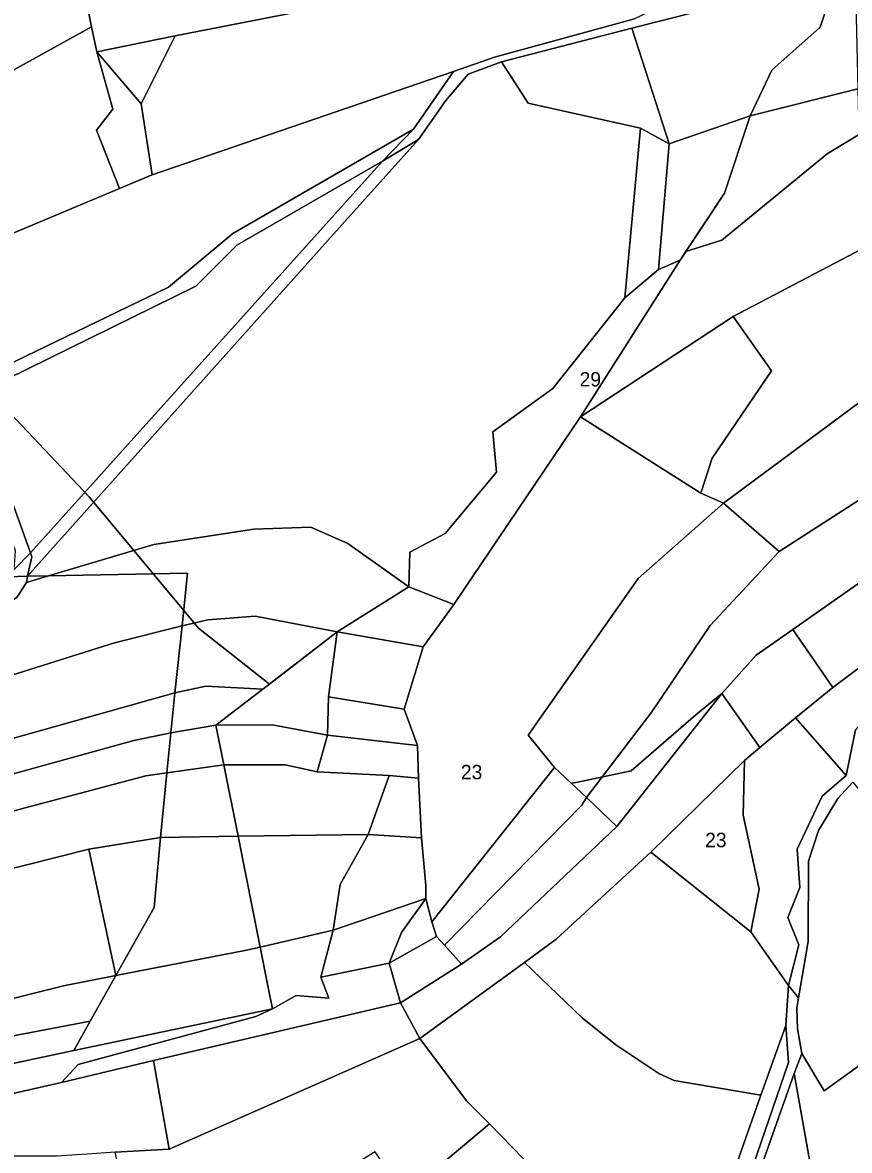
# Model space of a CAD drawing. Extents: x -521261 to -517465, y -1182764 to -1179456.
# Drawn here: x -520234.1 to -519947.3, y -1181487.6 to -1181096.5 of the extents above; entities that cross this region are included whole.
import ezdxf

# ---------------------------------------------------------------- set-up
doc = ezdxf.new("R2010")
doc.units = 0
for name, color, linetype in [('95560013', 7, 'Continuous'), ('95610013', 7, 'Continuous'), ('95620013', 7, 'Continuous'), ('95630013', 7, 'Continuous'), ('95640013', 7, 'Continuous'), ('95660013', 7, 'Continuous')]:
    doc.layers.add(name, color=color, linetype=linetype)

msp = doc.modelspace()

# ---------------------------------------------------------------- linework, layer by layer
at = {"layer": '95560013'}
for points in [[(-519951.3, -1181365.5), (-519946.1, -1181359.91), (-519939.45, -1181367.89), (-519928.16, -1181391.65), (-519920.19, -1181404.39), (-519905.49, -1181435.85), (-519925.87, -1181445.17), (-519955.99, -1181466.92), (-519963.8, -1181454), (-519965.32, -1181445.39), (-519965.55, -1181438.1), (-519964.94, -1181434.67), (-519961.63, -1181415.2), (-519961.5, -1181387.25), (-519958.05, -1181376.65)], [(-520016.12, -1181384.16), (-519981.47, -1181411.84), (-519968.45, -1181430.45), (-519969.29, -1181444.31), (-519978.05, -1181468.4), (-520008.07, -1181463.33), (-520013.39, -1181460.97), (-520028.29, -1181450.94), (-520039.97, -1181441.63), (-520059.93, -1181422.38), (-520049.04, -1181414.3)], [(-520059.93, -1181422.38), (-520039.97, -1181441.63), (-520028.29, -1181450.94), (-520013.39, -1181460.97), (-520008.07, -1181463.33), (-519978.05, -1181468.4), (-519996.47, -1181521.04), (-520018.3, -1181517.23), (-520033.36, -1181509.68), (-520056.39, -1181494.56), (-520072.1, -1181478.37), (-520080.04, -1181470.38), (-520096.25, -1181448.83)], [(-519881.06, -1181420.17), (-519881.55, -1181422.98), (-519869.95, -1181467.47), (-519852.44, -1181544.73), (-519850.41, -1181556.71), (-519864.72, -1181556.65), (-519890.05, -1181563.82), (-519912.71, -1181573.25), (-519943.88, -1181587.97), (-519966.4, -1181460.95), (-519963.8, -1181454), (-519955.99, -1181466.92), (-519925.87, -1181445.17), (-519905.49, -1181435.85), (-519894.06, -1181430.89)], [(-519968.45, -1181457.09), (-519991.41, -1181524.14), (-520014.78, -1181559.72), (-520031.11, -1181570.27), (-520050.83, -1181581.91), (-520073.58, -1181593.67), (-520103.45, -1181603.73), (-520078.6, -1181591.68), (-520045.34, -1181574.36), (-520019.1, -1181556.48), (-519998.04, -1181525.72), (-519996.47, -1181521.04), (-519978.05, -1181468.4), (-519969.29, -1181444.31)], [(-519980.74, -1181501.54), (-519966.4, -1181460.95), (-519943.88, -1181587.97), (-519965.56, -1181598.45)]]:
    msp.add_lwpolyline(points, close=True, dxfattribs=at)
msp.add_lwpolyline([(-519991.41, -1181524.14), (-519968.45, -1181457.09), (-519969.29, -1181444.31), (-519968.45, -1181430.45), (-519964.94, -1181434.67), (-519965.55, -1181438.1), (-519965.32, -1181445.39), (-519963.8, -1181454), (-519966.4, -1181460.95), (-519980.74, -1181501.54)], dxfattribs=at)
at = {"layer": '95610013'}
for points in [[(-520022.75, -1181098.44), (-520009.75, -1181138.53), (-520019.71, -1181133.07), (-520058.75, -1181124.43), (-520067.99, -1181110.15)], [(-520067.99, -1181110.15), (-520058.75, -1181124.43), (-520019.71, -1181133.07), (-520025.14, -1181191.93), (-520050.1, -1181223.4), (-520070.9, -1181238.45), (-520069.69, -1181252.35), (-520087.51, -1181273.69), (-520099.76, -1181280.17), (-520100.07, -1181292.11), (-520121.29, -1181277.16), (-520134.04, -1181271.49), (-520153.79, -1181272.12), (-520188.51, -1181277.48), (-520225.08, -1181288.33), (-520232.39, -1181288.47), (-520122.24, -1181165.49), (-520096.77, -1181137.02), (-520087.2, -1181123.58), (-520079.52, -1181114.4)], [(-519944.34, -1181119.43), (-519943.14, -1181175.07), (-519987.58, -1181198.4), (-520040.59, -1181233.21), (-520006.04, -1181178.85), (-519990.56, -1181155.71), (-519981.67, -1181128.85)], [(-520019.71, -1181133.07), (-520009.75, -1181138.53), (-520013.54, -1181182.09), (-520025.14, -1181191.93)], [(-519856.08, -1181205.45), (-519852.38, -1181211.59), (-519868.58, -1181228.75), (-519891.75, -1181243.42), (-519901.14, -1181260.79), (-519966.9, -1181306.97), (-519979.58, -1181315.88), (-519991.48, -1181329.17), (-520027.93, -1181375.27), (-520038.45, -1181365.21), (-520015.84, -1181335.46), (-519995.54, -1181305.59), (-519971.69, -1181279.96)], [(-519990.97, -1181263.2), (-519971.69, -1181279.96), (-519995.54, -1181305.59), (-520015.84, -1181335.46), (-520038.45, -1181365.21), (-520049.55, -1181354.85), (-520058.68, -1181343.58), (-520020.61, -1181289.25)], [(-520153.79, -1181272.12), (-520134.04, -1181271.49), (-520121.29, -1181277.16), (-520100.07, -1181292.11), (-520124.95, -1181307.73), (-520153.36, -1181302.35), (-520169.85, -1181303.56), (-520178.71, -1181305.72), (-520176.89, -1181287.4), (-520225.08, -1181288.33), (-520188.51, -1181277.48)], [(-520232.39, -1181288.47), (-520232.63, -1181290.61), (-520236.03, -1181295.81), (-520255.53, -1181307.58), (-520287.18, -1181334.21), (-520293.89, -1181340.02), (-520317.68, -1181359.9), (-520321.39, -1181363.01), (-520341.1, -1181374.15), (-520355.78, -1181386.73), (-520385.73, -1181412.26), (-520405.58, -1181428.65), (-520445.12, -1181472.67), (-520448.41, -1181473.09), (-520408.16, -1181427.45), (-520391.32, -1181413.46), (-520359.89, -1181386.72), (-520345.57, -1181373.71), (-520321.57, -1181359.96), (-520292.94, -1181335.11), (-520256.36, -1181304.34), (-520239.14, -1181288.67)], [(-520176.89, -1181287.4), (-520178.71, -1181305.72), (-520202.19, -1181311.58), (-520269.09, -1181332.61), (-520287.18, -1181334.21), (-520255.53, -1181307.58), (-520236.03, -1181295.81), (-520232.63, -1181290.61), (-520225.08, -1181288.33)], [(-520225.08, -1181288.33), (-520232.63, -1181290.61), (-520232.39, -1181288.47)], [(-520202.19, -1181311.58), (-520178.71, -1181305.72), (-520181.27, -1181328.86), (-520253.27, -1181349.13), (-520292.48, -1181357.65), (-520293.89, -1181340.02), (-520287.18, -1181334.21), (-520269.09, -1181332.61)], [(-520169.85, -1181303.56), (-520153.36, -1181302.35), (-520124.95, -1181307.73), (-520150.71, -1181327.64), (-520170.48, -1181326.56), (-520181.27, -1181328.86), (-520178.71, -1181305.72)], [(-520182.58, -1181342.83), (-520195.46, -1181345.45), (-520246.59, -1181359.49), (-520270.2, -1181364.68), (-520301.73, -1181370.53), (-520292.48, -1181357.65), (-520253.27, -1181349.13), (-520181.27, -1181328.86)], [(-520170.48, -1181326.56), (-520150.71, -1181327.64), (-520166.98, -1181340.15), (-520182.58, -1181342.83), (-520181.27, -1181328.86)], [(-519991.48, -1181329.17), (-519978.38, -1181347.83), (-519983.72, -1181352.35), (-520016.12, -1181384.16), (-520049.04, -1181414.3), (-520059.93, -1181422.38), (-520096.25, -1181448.83), (-520102.93, -1181436.39), (-520081.87, -1181423.03), (-520068.35, -1181413.48), (-520027.93, -1181375.27)], [(-520166.98, -1181340.15), (-520164.29, -1181353.89), (-520184.06, -1181356.65), (-520182.58, -1181342.83)], [(-520195.46, -1181345.45), (-520182.58, -1181342.83), (-520184.06, -1181356.65), (-520191.33, -1181357.73), (-520249.83, -1181373.13), (-520302.68, -1181384.22), (-520337.44, -1181387.17), (-520355.78, -1181386.73), (-520341.1, -1181374.15), (-520301.73, -1181370.53), (-520270.2, -1181364.68), (-520246.59, -1181359.49)], [(-520191.33, -1181357.73), (-520184.06, -1181356.65), (-520186.19, -1181379.03), (-520211.1, -1181383.08), (-520254.64, -1181394.05), (-520290.16, -1181400.78), (-520324.33, -1181405.78), (-520365.37, -1181407.48), (-520385.73, -1181412.26), (-520355.78, -1181386.73), (-520337.44, -1181387.17), (-520302.68, -1181384.22), (-520249.83, -1181373.13)], [(-520164.29, -1181353.89), (-520159.29, -1181378.66), (-520186.19, -1181379.03), (-520184.06, -1181356.65)], [(-520211.1, -1181383.08), (-520186.19, -1181379.03), (-520188.37, -1181403.38), (-520201.65, -1181426.98)], [(-520186.19, -1181379.03), (-520159.29, -1181378.66), (-520151.63, -1181417.07), (-520156.97, -1181418.3), (-520201.65, -1181426.98), (-520188.37, -1181403.38)], [(-520211.1, -1181383.08), (-520201.65, -1181426.98), (-520219.86, -1181430.55), (-520255.51, -1181439.46), (-520313.09, -1181448.84), (-520364.32, -1181456), (-520445.12, -1181472.67), (-520405.58, -1181428.65), (-520385.73, -1181412.26), (-520365.37, -1181407.48), (-520324.33, -1181405.78), (-520290.16, -1181400.78), (-520254.64, -1181394.05)], [(-520151.63, -1181417.07), (-520148.84, -1181431.11), (-520147.36, -1181438.44), (-520216.32, -1181452.99), (-520210.56, -1181442.77), (-520201.65, -1181426.98), (-520156.97, -1181418.3)], [(-520219.86, -1181430.55), (-520201.65, -1181426.98), (-520210.56, -1181442.77), (-520310.06, -1181461.77), (-520313.09, -1181448.84), (-520255.51, -1181439.46)], [(-520216.32, -1181452.99), (-520307.52, -1181472.34), (-520310.06, -1181461.77), (-520210.56, -1181442.77)]]:
    msp.add_lwpolyline(points, close=True, dxfattribs=at)
at = {"layer": '95620013'}
for points in [[(-519886.73, -1181149.7), (-519872.92, -1181175.6), (-519990.97, -1181263.2), (-519998.85, -1181259.72), (-519994.9, -1181247.54), (-519974.28, -1181217.29), (-519987.58, -1181198.4), (-519943.14, -1181175.07)], [(-519872.92, -1181175.6), (-519856.08, -1181205.45), (-519971.69, -1181279.96), (-519990.97, -1181263.2)], [(-519987.58, -1181198.4), (-519974.28, -1181217.29), (-519994.9, -1181247.54), (-519998.85, -1181259.72), (-520040.59, -1181233.21)], [(-520040.59, -1181233.21), (-519998.85, -1181259.72), (-519990.97, -1181263.2), (-520020.61, -1181289.25), (-520058.68, -1181343.58), (-520049.55, -1181354.85), (-520092.06, -1181408.32), (-520094.21, -1181400.28), (-520094.14, -1181395.72), (-520095.71, -1181379.23), (-520096.74, -1181358.49), (-520097.13, -1181347.16), (-520101.66, -1181334.59), (-520095.13, -1181312.91), (-520084.5, -1181298.3)], [(-520100.07, -1181292.11), (-520084.5, -1181298.3), (-520095.13, -1181312.91), (-520124.95, -1181307.73)], [(-520150.71, -1181327.64), (-520124.95, -1181307.73), (-520127.97, -1181330.34), (-520128.29, -1181343.57), (-520147.46, -1181339.96), (-520166.98, -1181340.15)], [(-520095.13, -1181312.91), (-520101.66, -1181334.59), (-520127.97, -1181330.34), (-520124.95, -1181307.73)], [(-520127.97, -1181330.34), (-520101.66, -1181334.59), (-520097.13, -1181347.16), (-520128.29, -1181343.57)], [(-520166.98, -1181340.15), (-520147.46, -1181339.96), (-520128.29, -1181343.57), (-520131.91, -1181356.33), (-520142.97, -1181353.92), (-520164.29, -1181353.89)], [(-520097.13, -1181347.16), (-520096.74, -1181358.49), (-520106.91, -1181357.61), (-520131.91, -1181356.33), (-520128.29, -1181343.57)], [(-519984.11, -1181371.39), (-519978.54, -1181396.94), (-519981.47, -1181411.84), (-520016.12, -1181384.16), (-519983.72, -1181352.35)], [(-520164.29, -1181353.89), (-520142.97, -1181353.92), (-520131.91, -1181356.33), (-520106.91, -1181357.61), (-520114.22, -1181378.03), (-520159.29, -1181378.66)], [(-520049.55, -1181354.85), (-520038.45, -1181365.21), (-520040.12, -1181367.85), (-520087.7, -1181416.4), (-520090.47, -1181413.37), (-520092.06, -1181408.32)], [(-520106.91, -1181357.61), (-520096.74, -1181358.49), (-520095.71, -1181379.23), (-520114.22, -1181378.03)], [(-520040.12, -1181367.85), (-520038.45, -1181365.21), (-520027.93, -1181375.27), (-520068.35, -1181413.48), (-520081.87, -1181423.03), (-520087.7, -1181416.4)], [(-520159.29, -1181378.66), (-520114.22, -1181378.03), (-520123.93, -1181395.37), (-520126.37, -1181411.25), (-520151.63, -1181417.07)], [(-520095.71, -1181379.23), (-520094.14, -1181395.72), (-520094.21, -1181400.28), (-520126.37, -1181411.25), (-520123.93, -1181395.37), (-520114.22, -1181378.03)], [(-520126.37, -1181411.25), (-520094.21, -1181400.28), (-520102.68, -1181412.01), (-520106.92, -1181422.67), (-520130.56, -1181427.5)], [(-520094.21, -1181400.28), (-520092.06, -1181408.32), (-520090.47, -1181413.37), (-520106.92, -1181422.67), (-520102.68, -1181412.01)], [(-520126.37, -1181411.25), (-520130.56, -1181427.5), (-520127.78, -1181434.85), (-520139.12, -1181433.91), (-520147.36, -1181438.44), (-520148.84, -1181431.11), (-520151.63, -1181417.07)], [(-520087.7, -1181416.4), (-520081.87, -1181423.03), (-520102.93, -1181436.39), (-520106.92, -1181422.67), (-520090.47, -1181413.37)], [(-520106.92, -1181422.67), (-520102.93, -1181436.39), (-520188.68, -1181456.43), (-520220.56, -1181464.03), (-520214.82, -1181457.85), (-520153.14, -1181441.18), (-520147.36, -1181438.44), (-520139.12, -1181433.91), (-520127.78, -1181434.85), (-520130.56, -1181427.5)], [(-520147.36, -1181438.44), (-520153.14, -1181441.18), (-520214.82, -1181457.85), (-520220.56, -1181464.03), (-520249.84, -1181470.67), (-520276.65, -1181475.26), (-520305.37, -1181477.77), (-520307.98, -1181477.97), (-520307.52, -1181472.34), (-520216.32, -1181452.99)], [(-520102.93, -1181436.39), (-520096.25, -1181448.83), (-520183.26, -1181487.11), (-520188.68, -1181456.43)], [(-520080.04, -1181470.38), (-520072.1, -1181478.37), (-520097.97, -1181500.05), (-520102.02, -1181502.48), (-520111.72, -1181488.08), (-520140.88, -1181505.85), (-520171.13, -1181520), (-520198.96, -1181527.88), (-520198.13, -1181505.28), (-520201.97, -1181488.21), (-520183.26, -1181487.11), (-520096.25, -1181448.83)], [(-520220.56, -1181464.03), (-520188.68, -1181456.43), (-520183.26, -1181487.11), (-520201.97, -1181488.21), (-520211.67, -1181488.9), (-520222.29, -1181489.55), (-520248.06, -1181489.62), (-520277.86, -1181490.96), (-520303.01, -1181492.71), (-520305.37, -1181477.77), (-520276.65, -1181475.26), (-520249.84, -1181470.67)], [(-520056.39, -1181494.56), (-520079.5, -1181516.84), (-520096.12, -1181530.34), (-520122.34, -1181546.18), (-520150.55, -1181560.01), (-520174.55, -1181568.61), (-520208.16, -1181578.29), (-520204.49, -1181561.93), (-520102.02, -1181502.48), (-520097.97, -1181500.05), (-520072.1, -1181478.37)]]:
    msp.add_lwpolyline(points, close=True, dxfattribs=at)
at = {"layer": '95630013'}
for points in [[(-519970.42, -1181083.14), (-519951.75, -1181081.08), (-519957.49, -1181098.06), (-519974.19, -1181113.01), (-519981.67, -1181128.85), (-520009.75, -1181138.53), (-520022.75, -1181098.44), (-520000.75, -1181092.9)], [(-519949.41, -1181080.84), (-519945.25, -1181079.6), (-519944.34, -1181119.43), (-519981.67, -1181128.85), (-519974.19, -1181113.01), (-519957.49, -1181098.06), (-519951.75, -1181081.08)]]:
    msp.add_lwpolyline(points, close=True, dxfattribs=at)
at = {"layer": '95640013'}
for points in [[(-519984.22, -1181051.71), (-520073.26, -1181079.95), (-520181.15, -1181101.08), (-520208.33, -1181106.65), (-520210.11, -1181097.99), (-520214.23, -1181077.46), (-520069.91, -1181056.82), (-520036.68, -1181046.43)], [(-519984.22, -1181051.71), (-519971.7, -1181060.63), (-519957.06, -1181073.24), (-520007.71, -1181088.34), (-520021.78, -1181095.18), (-520070.4, -1181108.55), (-520084.62, -1181113.41), (-520189.15, -1181149.27), (-520192.88, -1181124.68), (-520181.15, -1181101.08), (-520073.26, -1181079.95)], [(-520210.11, -1181097.99), (-520243.42, -1181116.34), (-520272.96, -1181130.65), (-520281.95, -1181113.37), (-520289.13, -1181105.34), (-520214.23, -1181077.46)], [(-520208.33, -1181106.65), (-520202.7, -1181126.58), (-520208.38, -1181133.79), (-520200.46, -1181154.03), (-520254.49, -1181176.66), (-520288.03, -1181193.76), (-520297.05, -1181192.49), (-520302.49, -1181183.79), (-520304.08, -1181171.38), (-520302.27, -1181151.64), (-520287.43, -1181140.94), (-520292.51, -1181161.26), (-520277.55, -1181144.55), (-520279.13, -1181132.17), (-520272.96, -1181130.65), (-520243.42, -1181116.34), (-520210.11, -1181097.99)], [(-520181.15, -1181101.08), (-520192.88, -1181124.68), (-520208.33, -1181106.65)], [(-520192.88, -1181124.68), (-520189.15, -1181149.27), (-520200.46, -1181154.03), (-520208.38, -1181133.79), (-520202.7, -1181126.58), (-520208.33, -1181106.65)], [(-520098.46, -1181133.43), (-520161.15, -1181169.69), (-520183.49, -1181188.27), (-520261.22, -1181225.79), (-520261.82, -1181224.94), (-520288.03, -1181193.76), (-520254.49, -1181176.66), (-520200.46, -1181154.03), (-520189.15, -1181149.27), (-520084.62, -1181113.41)], [(-520009.75, -1181138.53), (-519981.67, -1181128.85), (-519990.56, -1181155.71), (-520006.04, -1181178.85), (-520013.54, -1181182.09)], [(-520109.27, -1181144.59), (-520159.71, -1181173.72), (-520173.94, -1181187.85), (-520246.91, -1181223.77), (-520248.19, -1181228.92), (-520250.09, -1181234), (-520243.27, -1181247.26), (-520231.33, -1181280.35), (-520236.97, -1181286.19), (-520236.52, -1181279.68), (-520238.76, -1181273.9), (-520247.52, -1181249.42), (-520251.17, -1181239.95), (-520261.22, -1181225.79), (-520183.49, -1181188.27), (-520161.15, -1181169.69), (-520098.46, -1181133.43)], [(-520109.27, -1181144.59), (-520096.77, -1181137.02), (-520122.24, -1181165.49), (-520232.39, -1181288.47), (-520230.87, -1181281.73), (-520231.33, -1181280.35)], [(-520159.71, -1181173.72), (-520109.27, -1181144.59), (-520231.33, -1181280.35), (-520243.27, -1181247.26), (-520250.09, -1181234), (-520248.19, -1181228.92), (-520246.91, -1181223.77), (-520173.94, -1181187.85)], [(-520013.54, -1181182.09), (-520006.04, -1181178.85), (-520040.59, -1181233.21), (-520084.5, -1181298.3), (-520100.07, -1181292.11), (-520099.76, -1181280.17), (-520087.51, -1181273.69), (-520069.69, -1181252.35), (-520070.9, -1181238.45), (-520050.1, -1181223.4), (-520025.14, -1181191.93)], [(-519751.87, -1181190.47), (-519734.37, -1181182.89), (-519728.68, -1181193.73), (-519750.87, -1181207.64), (-519774.62, -1181212.01), (-519786.76, -1181215.56), (-519829.59, -1181238.74), (-519874.64, -1181267.05), (-519879.94, -1181274.06), (-519908.9, -1181293.64), (-519925.73, -1181306.64), (-519953.04, -1181327.12), (-519966.9, -1181306.97), (-519901.14, -1181260.79), (-519826.46, -1181216.65), (-519791.66, -1181201.16), (-519778.56, -1181195.39)], [(-520230.87, -1181281.73), (-520232.39, -1181288.47), (-520239.14, -1181288.67), (-520236.97, -1181286.19), (-520231.33, -1181280.35)], [(-519966.9, -1181306.97), (-519953.04, -1181327.12), (-519965.99, -1181337.63), (-519978.38, -1181347.83), (-519991.48, -1181329.17), (-519979.58, -1181315.88)], [(-519920.76, -1181313.19), (-519945.15, -1181341.8), (-519948.46, -1181357.6), (-519965.99, -1181337.63), (-519953.04, -1181327.12), (-519925.73, -1181306.64)], [(-519978.38, -1181347.83), (-519965.99, -1181337.63), (-519948.46, -1181357.6), (-519956.74, -1181364.72), (-519965.37, -1181383.15), (-519964.45, -1181396.37), (-519968.69, -1181406.86), (-519964.87, -1181416.32), (-519968.45, -1181430.45), (-519981.47, -1181411.84), (-519978.54, -1181396.94), (-519984.11, -1181371.39), (-519983.72, -1181352.35)]]:
    msp.add_lwpolyline(points, close=True, dxfattribs=at)
for points in [[(-520000.75, -1181092.9), (-520022.75, -1181098.44), (-520067.99, -1181110.15), (-520079.52, -1181114.4), (-520087.2, -1181123.58), (-520096.77, -1181137.02), (-520109.27, -1181144.59), (-520098.46, -1181133.43), (-520084.62, -1181113.41), (-520070.4, -1181108.55), (-520021.78, -1181095.18)], [(-519946.1, -1181359.91), (-519951.3, -1181365.5), (-519958.05, -1181376.65), (-519961.5, -1181387.25), (-519961.63, -1181415.2), (-519964.94, -1181434.67), (-519968.45, -1181430.45), (-519964.87, -1181416.32), (-519968.69, -1181406.86), (-519964.45, -1181396.37), (-519965.37, -1181383.15), (-519956.74, -1181364.72), (-519948.46, -1181357.6), (-519945.15, -1181341.8)]]:
    msp.add_lwpolyline(points, dxfattribs=at)
at = {"layer": '95660013'}
for points in [[(-519804, -1181096), (-519877.5, -1181096.5), (-519906.5, -1181112.5), (-519955, -1181142), (-519991.5, -1181172), (-520000, -1181174.62), (-520004.04, -1181175.86), (-519990.56, -1181155.71), (-519981.67, -1181128.85), (-520009.75, -1181138.53), (-520013.54, -1181182.09), (-520025.14, -1181191.93), (-520050.1, -1181223.4), (-520070.9, -1181238.45), (-520069.69, -1181252.35), (-520087.51, -1181273.69), (-520099.76, -1181280.17), (-520100.07, -1181292.11), (-520124.95, -1181307.73), (-520148.41, -1181325.86), (-520173, -1181306.5), (-520211, -1181261), (-520246, -1181224)], [(-519943.14, -1181175.07), (-519987.58, -1181198.4), (-520040.59, -1181233.21), (-520006.04, -1181178.85), (-520004.04, -1181175.86), (-520000, -1181174.62), (-519991.5, -1181172), (-519955, -1181142), (-519906.5, -1181112.5)], [(-520307.52, -1181472.34), (-520216.32, -1181452.99), (-520147.36, -1181438.44), (-520148.84, -1181431.11), (-520151.63, -1181417.07), (-520159.29, -1181378.66), (-520164.29, -1181353.89), (-520166.98, -1181340.15), (-520150.71, -1181327.64), (-520148.41, -1181325.86), (-520124.95, -1181307.73), (-520100.07, -1181292.11), (-520084.5, -1181298.3), (-520040.59, -1181233.21), (-519987.58, -1181198.4), (-519943.14, -1181175.07)], [(-519856.08, -1181205.45), (-519971.69, -1181279.96), (-519990.97, -1181263.2), (-520020.61, -1181289.25), (-520058.68, -1181343.58), (-520049.55, -1181354.85), (-520043.81, -1181360.21), (-520038.45, -1181365.21), (-520027.93, -1181375.27), (-520068.35, -1181413.48), (-520081.87, -1181423.03), (-520102.93, -1181436.39), (-520096.25, -1181448.83), (-520080.04, -1181470.38), (-520072.1, -1181478.37), (-520056.39, -1181494.56)], [(-519901.14, -1181260.79), (-519966.9, -1181306.97), (-519979.58, -1181315.88), (-519991.48, -1181329.17), (-520000.5, -1181336.5), (-520023, -1181356), (-520042, -1181360), (-520043.81, -1181360.21), (-520049.55, -1181354.85), (-520058.68, -1181343.58), (-520020.61, -1181289.25), (-519990.97, -1181263.2), (-519971.69, -1181279.96), (-519856.08, -1181205.45)], [(-520246, -1181224), (-520211, -1181261), (-520173, -1181306.5), (-520148.41, -1181325.86), (-520150.71, -1181327.64), (-520166.98, -1181340.15), (-520164.29, -1181353.89), (-520159.29, -1181378.66), (-520151.63, -1181417.07), (-520148.84, -1181431.11), (-520147.36, -1181438.44), (-520216.32, -1181452.99), (-520307.52, -1181472.34)], [(-519945.15, -1181341.8), (-519948.46, -1181357.6), (-519956.74, -1181364.72), (-519965.37, -1181383.15), (-519964.45, -1181396.37), (-519968.69, -1181406.86), (-519964.87, -1181416.32), (-519968.45, -1181430.45), (-519981.47, -1181411.84), (-519978.54, -1181396.94), (-519984.11, -1181371.39), (-519983.72, -1181352.35), (-519978.38, -1181347.83), (-519991.48, -1181329.17), (-519979.58, -1181315.88), (-519966.9, -1181306.97), (-519901.14, -1181260.79)], [(-520056.39, -1181494.56), (-520072.1, -1181478.37), (-520080.04, -1181470.38), (-520096.25, -1181448.83), (-520102.93, -1181436.39), (-520081.87, -1181423.03), (-520068.35, -1181413.48), (-520027.93, -1181375.27), (-520038.45, -1181365.21), (-520043.81, -1181360.21), (-520042, -1181360), (-520023, -1181356), (-520000.5, -1181336.5), (-519991.48, -1181329.17), (-519978.38, -1181347.83), (-519983.72, -1181352.35), (-520016.12, -1181384.16), (-519981.47, -1181411.84), (-519968.45, -1181430.45), (-519964.87, -1181416.32), (-519968.69, -1181406.86), (-519964.45, -1181396.37), (-519965.37, -1181383.15), (-519956.74, -1181364.72), (-519948.46, -1181357.6), (-519945.15, -1181341.8)]]:
    msp.add_lwpolyline(points, dxfattribs=at)
for points in [[(-520013.54, -1181182.09), (-520009.75, -1181138.53), (-519981.67, -1181128.85), (-519990.56, -1181155.71), (-520006.04, -1181178.85), (-520040.59, -1181233.21), (-520084.5, -1181298.3), (-520100.07, -1181292.11), (-520099.76, -1181280.17), (-520087.51, -1181273.69), (-520069.69, -1181252.35), (-520070.9, -1181238.45), (-520050.1, -1181223.4), (-520025.14, -1181191.93)], [(-520016.12, -1181384.16), (-519983.72, -1181352.35), (-519984.11, -1181371.39), (-519978.54, -1181396.94), (-519981.47, -1181411.84)]]:
    msp.add_lwpolyline(points, close=True, dxfattribs=at)

# ---------------------------------------------------------------- texts
for s, rotation, p in [('29', 360, (-520040.87, -1181222.69)), ('23', 0, (-520082.03, -1181358.89)), ('23', 0, (-519997.33, -1181382.44))]:
    msp.add_text(s, height=5, rotation=rotation, dxfattribs=at).set_placement(p)

doc.saveas('drawing.dxf')
